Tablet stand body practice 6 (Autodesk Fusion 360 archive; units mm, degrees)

design "mm-Tablet stand body practice 6" references "haas minimill"
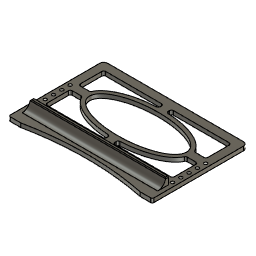
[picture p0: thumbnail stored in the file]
sketch "Sketch1" plane through (0, 0, 0) normal (0, 0, 1) x axis (1, 0, 0)
  line L1 (225.425, 0) -> (0, 0)
  line L2 (225.425, 149.225) -> (225.425, 0)
  line L3 (0, 149.225) -> (225.425, 149.225)
  line L4 (0, 0) -> (0, 149.225)
  point P1 (0, 0)
  point P2 (0, 0)
  point P3 (225.425, 0)
  point P5 (0, 149.225)
  horizontal L1
  vertical L2
  horizontal L3
  vertical L4
  coincident P1 P2
  dimension "d1" distance P2 P3 = 225.425
  dimension "d2" distance P2 P5 = 149.225
extrude "Extrude1" new body sketch "Sketch1" along normal blind 6.35
sketch "Sketch2" plane through (225.425, 0, 0) normal (1, 0, 0) x axis (0, 1, 0)
  line L1 (149.225, 0) -> (0, 0)
  line L2 (149.225, 6.35) -> (149.225, 0)
  line L3 (0, 6.35) -> (149.225, 6.35)
  line L4 (0, 0) -> (0, 6.35)
  line L5 (15.875, 6.35) -> (0, 6.35)
  line L6 (28.575, 6.35) -> (15.875, 6.35)
  line L7 (28.575, 17.907) -> (28.575, 6.35)
  line L8 (31.75, 17.907) -> (28.575, 17.907)
  line L9 (31.75, 6.35) -> (31.75, 17.907)
  line L10 (28.575, 6.35) -> (31.75, 6.35)
  line L11 (27.305, 6.35) -> (28.575, 6.35)
  line L12 (27.305, 16.637) -> (27.305, 6.35)
  line L13 (27.305, 16.637) -> (28.575, 17.907)
  line L14 (34.0111, 17.907) -> (28.575, 17.907)
  point P5 (0, 6.35)
  point P6 (0, 6.35)
  point P11 (31.75, 6.35)
  point P7 (15.875, 6.35)
  point P8 (28.575, 6.35)
  point P9 (28.575, 17.907)
  point P10 (31.75, 17.907)
  point P12 (27.305, 6.35)
  coincident P5 P6
  perpendicular L4 L5
  parallel L3 L6
  perpendicular L6 L7
  perpendicular L7 L8
  coincident L3 P11
  perpendicular L3 L9
  perpendicular L7 L11
  perpendicular L6 L12
  horizontal L14
  dimension "d5" distance P6 P7 = 15.875
  dimension "d6" distance P7 P8 = 12.7
  dimension "d8" distance P8 P9 = 11.557
  dimension "d9" distance P9 P10 = 3.175
  dimension "d10" distance P8 P12 = 1.27
  dimension "d11" angle L13 L14 = 135
extrude "Extrude2" add sketch "Sketch2" profile of L3 L6 L7 L8 L9 L10 L11 L12 L13 against normal blind 225.425
fillet "Fillet1" radius 12.7
sketch "Sketch3" plane through (0, 0, 6.35) normal (0, 0, 1) x axis (-1, 0, 0)
  line L1 (0, -14.8363) -> (-225.425, -14.8363)
  line L2 (0, 0) -> (0, -14.8363)
  line L3 (-225.425, 0) -> (0, 0)
  line L4 (-225.425, -14.8363) -> (-225.425, 0)
  line L5 (-19.05, 0) -> (0, 0)
  line L6 (-206.375, 0) -> (-225.425, 0)
  line L7 (-206.375, 0) -> (-19.05, 0)
  arc A1 centre (-112.7125, 457.2) radius 466.6953 clockwise from (-19.05, 0) to (-206.375, 0)
  point P4 (0, 0)
  point P6 (0, 0)
  point P5 (-225.425, 0)
  point P8 (-225.425, 0)
  point P7 (-19.05, 0)
  point P9 (-206.375, 0)
  point P10 (-112.7125, 457.2)
  coincident P4 P6
  perpendicular L2 L5
  coincident P5 P8
  perpendicular L4 L6
  dimension "d16" distance P6 P7 = 19.05
  dimension "d17" distance P8 P9 = 19.05
  dimension "d18" distance L3 P10 = 457.2
extrude "Extrude3" cut sketch "Sketch3" profile of L3 A1 L7 against normal blind 6.35
sketch "Sketch4" plane through (0, 0, 17.907) normal (0, 0, 1) x axis (-1, 0, 0)
  line L1 (-225.425, -31.75) -> (-225.425, -28.575)
  line L2 (0, -31.75) -> (-225.425, -31.75)
  line L3 (0, -28.575) -> (0, -31.75)
  line L4 (-225.425, -28.575) -> (0, -28.575)
  line L5 (-6.35, -31.75) -> (0, -31.75)
  line L6 (-6.35, -12.7) -> (-6.35, -31.75)
  line L7 (0, -12.7) -> (-6.35, -12.7)
  line L8 (0, -31.75) -> (0, -12.7)
  point P4 (0, -31.75)
  point P6 (0, -31.75)
  point P7 (-6.35, -31.75)
  point P9 (0, -12.7)
  horizontal L5
  vertical L6
  horizontal L7
  vertical L8
  coincident P4 P6
  dimension "d21" distance P6 P7 = 6.35
  dimension "d22" distance P6 P9 = 19.05
work_plane "WorkPlane1"
extrude "Extrude4" cut sketch "Sketch4" profile of L2 L3 L4 L5 L6 L7 L8 to an object
sketch "Sketch5" plane through (0, 0, 17.907) normal (0, 0, 1) x axis (-1, 0, 0)
  line L1 (-6.35, -28.575) -> (-6.35, -31.75)
  line L2 (-225.425, -28.575) -> (-6.35, -28.575)
  line L3 (-225.425, -31.75) -> (-225.425, -28.575)
  line L4 (-6.35, -31.75) -> (-225.425, -31.75)
  line L5 (-219.075, -31.75) -> (-225.425, -31.75)
  line L6 (-219.075, -12.7) -> (-219.075, -31.75)
  line L7 (-225.425, -12.7) -> (-219.075, -12.7)
  line L8 (-225.425, -31.75) -> (-225.425, -12.7)
  point P5 (-225.425, -31.75)
  point P6 (-225.425, -31.75)
  point P7 (-219.075, -31.75)
  point P9 (-225.425, -12.7)
  horizontal L5
  vertical L6
  horizontal L7
  vertical L8
  coincident P5 P6
  dimension "d25" distance P6 P7 = 6.35
  dimension "d26" distance P6 P9 = 19.05
extrude "Extrude5" cut sketch "Sketch5" profile of L2 L3 L4 L5 L6 L7 L8 to an object
chamfer "Chamfer1" distance 1.27
sketch "Sketch6" plane through (0, 0, 6.35) normal (0, 0, 1) x axis (-1, 0, 0)
  line L1 (-225.425, -149.225) -> (-225.425, 0)
  line L2 (0, -149.225) -> (-225.425, -149.225)
  line L3 (0, 0) -> (0, -149.225)
  line L4 (-19.05, 0) -> (0, 0)
  line L5 (-225.425, 0) -> (-206.375, 0)
  line L6 (-219.075, -14.8363) -> (-219.075, -31.75)
  line L7 (-6.35, -14.8363) -> (-219.075, -14.8363)
  line L8 (-6.35, -31.75) -> (-6.35, -14.8363)
  line L9 (-219.075, -31.75) -> (-6.35, -31.75)
  line L10 (-112.7125, -31.75) -> (-112.7125, -149.225)
  line L11 (-225.425, -90.4875) -> (-112.7125, -90.4875)
  curve K1 (-188.9125, -90.4875) -> (-36.5125, -90.4875)
  curve K2 (-112.7125, -122.2375) -> (-112.7125, -58.7375)
  arc A1 centre (-112.7125, 457.2) radius 466.6953 clockwise from (-19.05, 0) to (-206.375, 0)
  closed curve K3 centre (-112.7125, -90.4875)
  point P13 (-112.7125, -149.225)
  point P14 (-112.7125, -31.75)
  point P15 (-112.7125, -90.4875)
  point P18 (-36.5125, -90.4875)
  point P19 (-188.9125, -90.4875)
  point P20 (-112.7125, -58.7375)
  point P21 (-112.7125, -122.2375)
  point P17 (-112.7125, -90.4875)
  point P16 (-225.425, -90.4875)
  midpoint L2 P13
  midpoint L9 P14
  midpoint L10 P15
  perpendicular L10 L11
  coincident K3 P18
  coincident K3 P19
  coincident K3 P20
  coincident K3 P21
  coincident P15 P17
  perpendicular L10 K1
  coincident L1 P16
  dimension "d37" distance K3 = 152.4
  dimension "d38" = 31.75
extrude "Extrude6" cut sketch "Sketch6" profile of L10 L11 K3 no distance stored
sketch "Sketch7" plane through (0, 0, 6.35) normal (0, 0, 1) x axis (-1, 0, 0)
  line L1 (-212.725, -136.525) -> (-12.7, -136.525)
  line L2 (-212.725, -44.45) -> (-212.725, -136.525)
  line L3 (-12.7, -44.45) -> (-212.725, -44.45)
  line L4 (-12.7, -136.525) -> (-12.7, -44.45)
  line L5 (-225.425, -149.225) -> (-225.425, 0)
  line L6 (0, -149.225) -> (-225.425, -149.225)
  line L7 (0, 0) -> (0, -149.225)
  line L8 (-19.05, 0) -> (0, 0)
  line L9 (-225.425, 0) -> (-206.375, 0)
  line L10 (-219.075, -14.8363) -> (-219.075, -31.75)
  line L11 (-6.35, -14.8363) -> (-219.075, -14.8363)
  line L12 (-6.35, -31.75) -> (-6.35, -14.8363)
  line L13 (-219.075, -31.75) -> (-6.35, -31.75)
  line L14 (-106.3625, -90.4875) -> (-112.7125, -90.4875)
  line L15 (-112.7125, -44.45) -> (-112.7125, -90.4875)
  line L16 (-112.7125, -136.525) -> (-112.7125, -90.4875)
  line L17 (-106.3625, -84.1375) -> (-106.3625, -90.4875)
  line L18 (-106.3625, -44.45) -> (-106.3625, -52.5004)
  line L19 (-119.0625, -84.1375) -> (-119.0625, -90.4875)
  line L20 (-119.0625, -44.45) -> (-119.0625, -52.5004)
  line L21 (-106.3625, -122.1271) -> (-106.3625, -90.4875)
  line L22 (-106.3625, -136.525) -> (-106.3625, -128.4746)
  line L23 (-119.0625, -122.1271) -> (-119.0625, -90.4875)
  line L24 (-119.0625, -136.525) -> (-119.0625, -128.4746)
  line L25 (-119.0625, -84.1375) -> (-112.7125, -84.1375)
  line L26 (-212.725, -84.1375) -> (-194.1079, -84.1375)
  line L27 (-119.0625, -96.8375) -> (-112.7125, -96.8375)
  line L28 (-212.725, -96.8375) -> (-194.1079, -96.8375)
  line L29 (-119.0625, -90.4875) -> (-112.7125, -90.4875)
  line L30 (-195.2625, -90.4875) -> (-188.9125, -90.4875)
  line L31 (-38.0521, -84.1375) -> (-112.7125, -84.1375)
  line L32 (-12.7, -84.1375) -> (-31.3171, -84.1375)
  line L33 (-38.0521, -96.8375) -> (-112.7125, -96.8375)
  line L34 (-12.7, -96.8375) -> (-31.3171, -96.8375)
  closed curve K1 centre (-112.7125, -90.4875)
  arc A1 centre (-112.7125, 457.2) radius 466.6953 clockwise from (-19.05, 0) to (-206.375, 0)
  closed curve K2 centre (-112.7125, -90.4875)
  closed curve K3 centre (-112.7125, -90.4875)
  point P6 (-112.7125, -90.4875)
  point P20 (-112.7125, -90.4875)
  point P18 (-112.7125, -90.4875)
  point P21 (-112.7125, -90.4875)
  point P22 (-112.7125, -44.45)
  point P23 (-112.7125, -90.4875)
  point P24 (-112.7125, -136.525)
  point P39 (-106.3625, -84.1375)
  point P41 (-119.0625, -52.5004)
  point P42 (-106.3625, -52.5004)
  point P43 (-106.3625, -122.1271)
  point P44 (-106.3625, -128.4746)
  point P45 (-119.0625, -122.1271)
  point P46 (-119.0625, -128.4746)
  point P47 (-119.0625, -96.8375)
  point P48 (-194.1079, -96.8375)
  point P49 (-194.1079, -84.1375)
  point P50 (-188.9125, -90.4875)
  point P51 (-195.2625, -90.4875)
  point P52 (-38.0521, -84.1375)
  point P53 (-31.3171, -84.1375)
  point P54 (-38.0521, -96.8375)
  point P55 (-31.3171, -96.8375)
  horizontal L1
  vertical L2
  horizontal L3
  vertical L4
  coincident P6 P20
  perpendicular L2 L29
  coincident P18 P21
  midpoint L3 P22
  perpendicular L3 L15
  coincident P18 P23
  midpoint L1 P24
  coincident P39 L31
  collinear L17 L18
  collinear L19 L20
  coincident K3 P41
  coincident K3 P42
  coincident K1 P43
  coincident K3 P44
  collinear L21 L22
  coincident K1 P45
  coincident K3 P46
  collinear L23 L24
  collinear L25 L26
  coincident L23 P47
  collinear L27 L28
  coincident K3 P48
  coincident K3 P49
  coincident K1 P50
  collinear L29 L30
  coincident K3 P51
  coincident K1 P52
  coincident K3 P53
  collinear L31 L32
  coincident K1 P54
  coincident K3 P55
  collinear L33 L34
  dimension "d65" distance L1 L6 = 12.7
  dimension "d66" distance L2 L5 = 12.7 (= "d65")
  dimension "d67" distance L3 L13 = 12.7
  dimension "d68" = 38.1
extrude "Extrude7" cut sketch "Sketch7" profile of L1 L2 L3 L4 K3 L24 L22 L26 L32 L28 L34 L18 L20 no distance stored
fillet "Fillet2" radius 3
fillet "Fillet3" radius 3
hole "Hole1" HoleDepth 35.56 HoleDiameter 5.035 TipAngle 118 RefDim1 6.35 RefDim2 38.1
rectangular_pattern "R-Pattern1" uSpaceDistance -52.07 vSpaceDistance 212.725
fillet "Fillet4" radius 6
fillet "Fillet5" radius 2.5
fillet "Fillet6" radius 2.5
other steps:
thread "Thread1"

design "haas minimill"
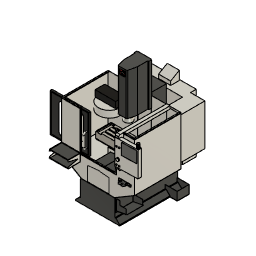
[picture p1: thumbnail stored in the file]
